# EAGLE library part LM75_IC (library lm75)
Temperatursensor
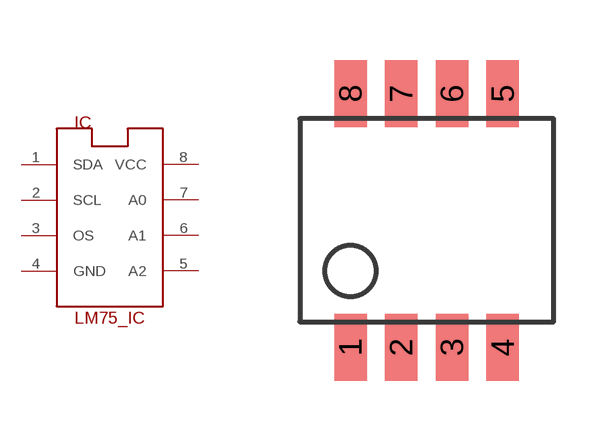
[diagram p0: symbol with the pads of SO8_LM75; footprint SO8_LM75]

Designator prefix IC

## LM75_ICN  [SO8_LM75]
1  SDA
2  SCL
3  OS  out
4  GND  pwr
5  A2  in
6  A1  in
7  A0  in
8  VCC  pwr

## Footprint SO8_LM75 (pad centres in mm)
smd 0.813 x 1.676: 1 -1.27,-3.175; 2 0,-3.175; 3 1.27,-3.175; 4 2.54,-3.175; 5 2.54,3.175; 6 1.27,3.175; 7 0,3.175; 8 -1.27,3.175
